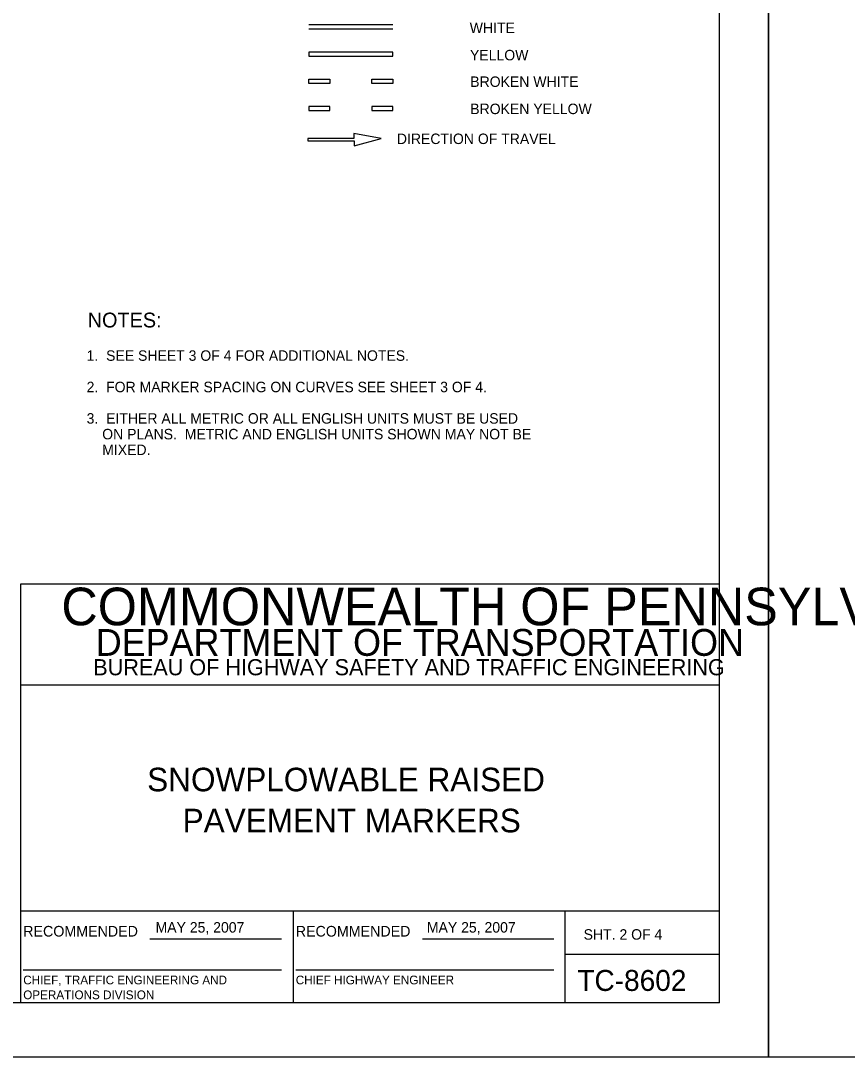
# Model space of a CAD drawing. Extents: x 639362 to 641108, y 298458 to 299646.
# Drawn here: x 639989.3 to 640225.9, y 298457.6 to 298754.5 of the extents above; entities that cross this region are included whole.
import ezdxf

# ---------------------------------------------------------------- set-up
doc = ezdxf.new("R2010")
doc.units = 0
for name, color, linetype in [('1', 7, 'Continuous'), ('2', 7, 'Continuous'), ('PLT-BNDY', 7, 'Continuous')]:
    doc.layers.add(name, color=color, linetype=linetype)

msp = doc.modelspace()

# ---------------------------------------------------------------- linework, layer by layer
at = {"layer": '1'}
for p, q in [((640189.27, 298473.19), (640189.27, 299037.19)), ((639989.27, 298473.19), (639989.27, 298593.19)), ((639989.27, 298593.19), (640189.27, 298593.19)), ((640189.27, 298564.19), (639989.27, 298564.19)), ((639989.27, 298499.57), (640189.27, 298499.57)), ((640067.27, 298499.57), (640067.27, 298473.19)), ((640145.15, 298473.19), (640145.15, 298499.57)), ((640026.24, 298491.57), (640063.87, 298491.57)), ((640104.24, 298491.57), (640141.87, 298491.57)), ((640145.15, 298487.19), (640189.27, 298487.19)), ((639989.99, 298482.68), (640063.87, 298482.68)), ((640067.99, 298482.68), (640141.87, 298482.68)), ((640189.27, 298473.19), (639403.27, 298473.19))]:
    msp.add_line(p, q, dxfattribs=at)
at = {"layer": '2'}
for p, q in [((640095.79, 298753.36), (640071.74, 298753.36)), ((640095.79, 298752.16), (640071.74, 298752.16)), ((640095.79, 298745.55), (640071.74, 298745.55)), ((640071.74, 298745.55), (640071.74, 298744.35)), ((640095.79, 298744.35), (640095.79, 298745.55)), ((640071.74, 298744.35), (640095.79, 298744.35)), ((640071.74, 298737.77), (640077.75, 298737.77)), ((640089.78, 298737.77), (640095.79, 298737.77)), ((640077.75, 298729.98), (640071.74, 298729.98)), ((640095.79, 298729.98), (640089.78, 298729.98)), ((640092.46, 298720.77), (640084.66, 298722.25)), ((640084.66, 298722.25), (640084.66, 298720.81)), ((640084.66, 298720.81), (640071.41, 298720.81)), ((640071.41, 298720.81), (640071.41, 298720.1)), ((640071.41, 298720.1), (640084.74, 298720.1)), ((640084.74, 298718.66), (640092.46, 298720.77)), ((640084.74, 298720.1), (640084.74, 298718.66))]:
    msp.add_line(p, q, dxfattribs=at)
for points in [[(640077.75, 298737.77), (640077.75, 298736.57), (640071.74, 298736.57), (640071.74, 298737.77)], [(640095.79, 298737.77), (640095.79, 298736.57), (640089.78, 298736.57), (640089.78, 298737.77)], [(640071.74, 298729.98), (640071.74, 298728.78), (640077.75, 298728.78), (640077.75, 298729.98)], [(640089.78, 298729.98), (640089.78, 298728.78), (640095.79, 298728.78), (640095.79, 298729.98)]]:
    msp.add_lwpolyline(points, dxfattribs=at)
at = {"layer": 'PLT-BNDY'}
for points in [[(639362.31, 299051.63), (640203.31, 299051.63), (640203.31, 298457.63), (639362.31, 298457.63)], [(640203.31, 299051.63), (641044.31, 299051.63), (641044.31, 298457.63), (640203.31, 298457.63)]]:
    msp.add_lwpolyline(points, close=True, dxfattribs=at)

# ---------------------------------------------------------------- texts
at = {"layer": '1'}
for s, height, p in [('COMMONWEALTH OF PENNSYLVANIA', 10.7828, (640000.9, 298581.36)), ('DEPARTMENT OF TRANSPORTATION', 7.6837, (640010.76, 298572.61)), ('BUREAU OF HIGHWAY SAFETY AND TRAFFIC ENGINEERING', 4.6253, (640010.04, 298567.04)), ('SNOWPLOWABLE RAISED', 6.75, (640025.46, 298533.81)), ('PAVEMENT MARKERS', 6.75, (640035.61, 298522.06)), ('RECOMMENDED', 3.048, (639989.99, 298492.2)), ('RECOMMENDED', 3.048, (640067.99, 298492.2)), ('SHT. 2 OF 4', 3, (640150.4, 298491.31)), ('CHIEF, TRAFFIC ENGINEERING AND', 2.5, (639989.99, 298478.51)), ('CHIEF HIGHWAY ENGINEER', 2.5, (640067.99, 298478.51)), ('TC-8602', 6, (640148.6, 298476.63)), ('OPERATIONS DIVISION', 2.5, (639989.99, 298474.26))]:
    msp.add_text(s, height=height, dxfattribs=at).set_placement(p)
at = {"layer": '2'}
for s, height, p in [('WHITE', 3, (640117.79, 298750.98)), ('YELLOW', 3, (640117.87, 298743.18)), ('BROKEN WHITE', 3, (640117.94, 298735.57)), ('BROKEN YELLOW', 3, (640117.94, 298727.78)), ('DIRECTION OF TRAVEL', 3, (640096.94, 298719.21)), ('NOTES:', 4.25, (640008.44, 298666.67)), ('1.  SEE SHEET 3 OF 4 FOR ADDITIONAL NOTES.', 3, (640008.13, 298657.12)), ('2.  FOR MARKER SPACING ON CURVES SEE SHEET 3 OF 4.', 3, (640008.13, 298648.12)), ('3.  EITHER ALL METRIC OR ALL ENGLISH UNITS MUST BE USED', 3, (640008.13, 298639.12)), ('    ON PLANS.  METRIC AND ENGLISH UNITS SHOWN MAY NOT BE', 3, (640008.13, 298634.62)), ('    MIXED.', 3, (640008.13, 298630.12)), ('MAY 25, 2007', 3, (640027.86, 298493.34)), ('MAY 25, 2007', 3, (640105.52, 298493.34))]:
    msp.add_text(s, height=height, dxfattribs=at).set_placement(p)

doc.saveas('drawing.dxf')
